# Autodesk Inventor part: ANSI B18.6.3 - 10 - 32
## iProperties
Comments: To add or edit properties for Autodesk Inventor files, use iProperties.
Created: 2005-01
Part Number: ANSI B18.6.3 - 10 - 32
Vendor: Autodesk Inc.
Document SubType Name: Modeling
Designer: John Blackburn
Material: Default
Description: Hex Machine Screw Nut UNF
Standard: ANSI B18.6.3
Alert: To add or edit properties for Autodesk Inventor files, use iProperties.
Control State: 0
Master: False
Checked Out: False
Shininess: 64.0
Length Units: 11272
Angle Units: 11279
Time Units: 11290
Mass Units: 11286
Length Display Precision: 3
Angle Display Precision: 2
Compacted: True
EGR: 4
Classification: un/spsc 31161727
Density: 0.0
Volumn: 0.0
Area: 0.0
PropertySet Name: Model Information
Author: John Blackburn
Revision Number: 8
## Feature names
1. Body [Extrusion]
2. Chamfer1 [Revolution]
3. Thread [Hole]
4. Chamfer2
5. Chamfer3
